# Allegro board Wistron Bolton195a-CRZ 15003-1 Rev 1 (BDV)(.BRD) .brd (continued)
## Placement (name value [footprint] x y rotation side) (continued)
PC4914  SC4D7U6D3V3KX-GP  [C603H36]  81.03 35.64 90 top
PC4915  SC1U6D3V2KX-GP  [C402H22]  86.84 37.5 270 top
PC4916  SC22P50V2JN-4DLGP  [C402H22]  71.11 26.53 270 top
PC4917  SC1U25V3KX-1-GP  [C603H36]  74.05 35.88 180 top
PC4918  SC22P50V2JN-4DLGP  [C402H22]  71.19 36.46 90 top
PC4919  SC18P50V2JN-1DLGP  [C402H22]  71.12 33.52 270 top
PC4920  SC18P50V2JN-1DLGP  [C402H22]  71.12 30.54 270 top
PC4921  SCD1U16V2KX-3GP  [C402H22]  73.26 24.94 90 top
PC4922  SC10U25V6KX-1GP  [C1206H71]  92.91 21 270 top
PC4923  SC10U25V6KX-1GP  [C1206H71]  92.91 23.22 270 top
PC5001  SC1U10V2KX-1GP  [C402H22]  110.95 127.2 270 bottom
PC5002  SC1KP50V2KX-1DLGP  [C402H22]  110.95 126.32 270 bottom
PC5005  SCD1U50V3KX-GP  [C603H36]  114.63 135.15 90 bottom
PC5006  SC10U25V6KX-1GP  [C1206H71]  114.49 131.25 90 bottom
PC5007  SC10U25V6KX-1GP  [C1206H71]  114.49 133.44 90 bottom
PC5008  SCD1U50V3KX-GP  [C603H36]  112.89 125.57 180 bottom
PC5009  SC10U10V5KX-2GP  [C805H54]  114.48 118.4 180 bottom
PC5010  SC1KP50V2KX-1GP  [C402H22]  111.81 140.58 0 top
PC5011  SCD1U16V2KX-3GP  [C402H22]  114.2 153.55 0 bottom
PC5012  SC22U6D3V3MX-1-GP  [C603H40]  115.28 153.66 0 bottom
PC5013  SC18P50V2JN-1DLGP  [C402H22]  107.76 118.17 90 bottom
PC5014  SC10U10V5KX-2DLGP  [C805H50]  112.26 113.32 180 bottom
PC5015  SC10U10V5KX-2GP  [C805H54]  110.08 113.32 180 bottom
PC5016  SCD033U25V3KX-GP  [C603]  109.79 117.17 180 bottom
PC5101  SC10U6D3V3MX-GP  [C603H38]  14.31 132.52 90 top
PC5102  SC10U6D3V3MX-GP  [C603H38]  14.31 131.25 90 top
PC5103  SC1U6D3V2KX-GP  [C402H22]  10.89 135.91 180 top
PC5104  SC1KP50V2KX-1DLGP  [C402H22]  16.61 135.52 180 bottom
PC5105  SC22U6D3V3MX-1-GP  [C603H40]  28.17 132.5 90 top
PC5106  SC22U6D3V3MX-1-GP  [C603H40]  28.16 131.3 90 top
PC5107  SC22U6D3V3MX-1-DL-GP  [C603H40]  28.16 130.12 90 top
PC5108  SC22P50V2JN-4GP  [C402H22]  11.08 137.84 180 top
PC5109  SC680P50V2KX-2DLGP  [C402H22]  12.74 138.15 90 top
PC5110  SCD1U10V2KX-5DLGP  [C402H22]  16 138.47 270 top
PC5203  SCD1U10V2KX-5DLGP  [C402H22]  53.08 20 0 top
PC5204  SC1U10V2KX-1GP  [C402H22]  108.76 126.24 90 bottom
PC5205  SC22U6D3V3MX-1-GP  [C603H40]  51.26 20.35 90 top
PC5206  SC22U6D3V3MX-1-GP  [C603H40]  51.46 27.36 180 top
PC5207  SC22U6D3V3MX-1-GP  [C603H40]  116.51 153.66 0 bottom
PC5208  SCD1U50V3KX-GP  [C603H36]  77.73 36.11 270 top
PC5210  SC22U6D3V3MX-1-GP  [C603H40]  24.88 164.16 90 top
PC5211  SC22U6D3V3MX-1-GP  [C603H40]  24.88 162.97 90 top
PC5212  SC22U6D3V3MX-1-GP  [C603H40]  24.88 161.77 90 top
PC5213  SC22U6D3V3MX-1-GP  [C603H40]  24.88 160.55 90 top
PC5214  SC22U6D3V3MX-1-GP  [C603H40]  24.88 159.33 90 top
PC5215  SC22U6D3V3MX-1-GP  [C603H40]  24.89 158.12 90 top
PC5216  SC22U6D3V3MX-1-GP  [C603H40]  44.93 175.67 90 bottom
PC5217  SC22U6D3V3MX-1-GP  [C603H40]  44.93 176.86 90 bottom
PC5218  SC22U6D3V3MX-1-GP  [C603H40]  44.93 178.05 90 bottom
PC5219  SC22U6D3V3MX-1-GP  [C603H40]  44.93 179.25 90 bottom
PC5220  SC22U6D3V3MX-1-GP  [C603H40]  44.93 180.44 90 bottom
PC5221  SC22U6D3V3MX-1-GP  [C603H40]  44.93 181.64 90 bottom
PC5222  SC22U6D3V3MX-1-GP  [C603H40]  66.09 182.17 270 bottom
PC5223  SC22U6D3V3MX-1-GP  [C603H40]  66.09 180.9 270 bottom
PC5224  SC22U6D3V3MX-1-GP  [C603H40]  44.93 173.25 90 bottom
PC5225  SC22U6D3V3MX-1-GP  [C603H40]  44.93 174.45 90 bottom
PC5226  SC22U6D3V3MX-1-GP  [C603H40]  44.96 182.85 90 bottom
PC5229  SC22U6D3V3MX-1-GP  [C603H40]  44.93 172.03 90 bottom
PG4401  COPPER-CLOSE-GP-U  [CON2C-U]  16.66 171.4 0 top
PG4402  COPPER-CLOSE-GP-U  [CON2C-U]  16.66 168.55 180 top
PG4403  COPPER-CLOSE-GP-U  [CON2C-U]  55.57 179.49 180 top
PG4404  COPPER-CLOSE-GP-U  [CON2C-U]  55.42 184.87 0 top
PG4801  GAP-CLOSE-PWR-3-GP  [GAP-CLOSE-PWR-3]  29.52 116.81 270 top
PG4802  GAP-CLOSE-PWR-3-GP  [GAP-CLOSE-PWR-3]  62.79 139.27 0 bottom
PG4901  GAP-CLOSE-PWR-3-GP  [GAP-CLOSE-PWR-3]  80.55 33.87 0 top
PG4902  GAP-CLOSE-PWR-3-GP  [GAP-CLOSE-PWR-3]  70.78 24.2 270 top
PG4903  GAP-CLOSE-PWR-3-GP  [GAP-CLOSE-PWR-3]  86.89 38.45 180 top
PG4904  GAP-CLOSE-PWR-3-GP  [GAP-CLOSE-PWR-3]  81.48 37.19 0 top
PG4905  GAP-CLOSE-PWR-3-GP  [GAP-CLOSE-PWR-3]  113.13 153.5 90 bottom
PL4901  IND-3D3UH-116-GP-U  [L686647-127318H119]  86.35 16.05 90 top
PL4902  IND-3D3UH-116-GP-U  [L686647-127318H119]  92.55 34.15 180 top
PL4904  IND-D36UH-19-GP  [L115100-2H158]  55.52 182.14 0 top
PL4905  IND-D33UH-12-GP-U  [L686647-127318H119]  16.66 170.03 0 top
PL4906  IND-1D5UH-53-GP-U  [L686647-127318H119]  22.44 125.71 90 top
PL5001  IND-1D5UH-53-GP-U  [L686647-127318H119]  114.86 146.97 0 bottom
PL5101  IND-1D5UH-53-GP-U  [L686647-127318H119]  22.26 133.39 90 top
PQ4401  AON6520-GP  [PPAK-8P-5262H40]  13.64 179.78 0 top
PQ4402  AON6510-GP  [PPAK-8P-5262H40]  20.24 178 180 top
PQ4403  AON6520-GP  [PPAK-8P-5262H40]  67.37 189.83 90 bottom
PQ4404  AON6510-GP  [PPAK-8P-5262H40]  58.72 189.13 0 bottom
PQ4405  AON6510-GP  [PPAK-8P-5262H40]  52.16 189.15 0 bottom
PQ4801  AON7410-GP  [PPAK-8P-3232H36]  14.54 127.37 90 top
PQ4802  AON7506-GP  [PPAK-8P-3232H36]  16.05 122.97 270 top
PQ4901  AON7410-GP  [PPAK-8P-3232H36]  94.29 17.5 270 top
PQ4902  AON7410-GP  [PPAK-8P-3232H36]  94.98 26.24 180 top
PQ4903  AON7506-GP  [PPAK-8P-3232H36]  92.8 13.04 90 top
PQ4904  AON7506-GP  [PPAK-8P-3232H36]  90.53 27.74 0 top
PQ5001  AON7410-GP  [PPAK-8P-3232H36]  116.81 138.81 0 bottom
PQ5002  AON7506-GP  [PPAK-8P-3232H36]  112.39 140.31 180 bottom
PR1  D01R2512F-3-GP  [R2512H32]  126.75 16.26 270 top
PR2  300KR2F-GP  [R402H16]  126.24 8.46 0 bottom
PR3  30KR2F-GP  [R402H16]  121.26 11.89 270 bottom
PR4  30KR2F-GP  [R402H16]  132.16 14.25 0 top
PR7  300KR2F-GP  [R402H16]  129.57 13.51 270 top
PR10  15KR2F-GP  [R402H16]  127.94 6.88 90 bottom
PR11  15KR2F-GP  [R402H16]  118.59 10.92 90 bottom
PR12  100KR2F-L1-GP  [R402H16]  116.05 12.65 0 top
PR13  15KR2F-GP  [R402H16]  116.56 10.92 90 bottom
PR14  20KR2J-L2-GP  [R402H16]  109.6 18.99 180 top
PR15  20KR2J-L2-GP  [R402H16]  110.75 18.95 180 top
PR16  100KR2F-L1-GP  [R402H16]  115.01 12.65 180 top
PR17  200KR2F-L-GP  [R402H16]  119.51 20.16 0 top
PR18  100KR2J-1-GP  [R402H16]  116.41 19.74 270 top
PR161  10KR2J-3-GP  [R402H16]  36.07 75.18 270 top
PR4202  10KR2F-2-GP  [R402H16]  128.35 8.46 180 bottom
PR4401  27K4R2F-GP  [R402H16]  33.56 177.57 270 top
PR4402  10R2F-L-GP  [R402H14]  27.22 179.07 0 top
PR4403  0R0402-PAD-2-GP  [0R0402-PAD-1]  28.28 179.08 0 top
PR4404  2K05R2F-GP  [R402H16]  27.19 187.62 180 top
PR4405  -  [0R0805-PAD]  16.77 192.56 180 top
PR4406  -  [0R0805-PAD]  18.77 192.56 180 top
PR4407  499R2F-2-GP  [R402H16]  26.76 186 270 top
PR4408  5K62R2F-DL-GP  [R402H16]  32.33 189.12 270 bottom
PR4409  10R2F-L-GP  [R402H14]  27.63 181.19 270 top
PR4410  2K61R2F-1-GP  [R402H16]  32.57 179.08 0 top
PR4411  267KR2F-GP  [R402H16]  28.68 187.19 90 top
PR4412  1K6R2F-GP  [R402H16]  28.23 185.72 0 top
PR4413  825R2F-GP  [R402H16]  29.65 181.11 180 top
PR4414  11KR2F-L-GP  [R402H16]  31.16 183.55 270 top
PR4415  2D2R5J-1-GP  [R805H24]  15.06 179.55 180 bottom
PR4416  NTC-10K-27-GP-U  [NTC-402H24-U]  12.37 169.34 180 top
PR4417  2D2R5J-1-GP  [R805H24]  28.18 194.18 270 top
PR4418  1K2R2F-1-GP  [R402H16]  30.27 184.59 270 top
PR4420  2D2R5J-1-GP  [R805H24]  20.44 180.83 0 bottom
PR4421  3K83R2F-GP  [R402H16]  34 176.09 180 top
PR4422  NTC-470K-8-GP-U  [NTC-402H22-U]  11.3 183.49 90 top
PR4423  3K65R2F-1-GP  [R402H16]  31.5 179.08 180 top
PR4424  10R2F-L-GP  [R402H14]  29.97 177.89 270 top
PR4425  133KR2F-GP  [R402H16]  33.24 187.06 180 bottom
PR4426  1R5J-2-GP  [R805H24]  31.77 196.33 0 top
PR4427  1R5J-2-GP  [R805H24]  33.73 196.33 0 top
PR4428  0R0402-PAD-2-GP  [0R0402-PAD-1]  33.51 182.54 180 top
PR4429  0R0402-PAD-2-GP  [0R0402-PAD-1]  36.1 179.21 180 top
PR4430  0R0402-PAD-2-GP  [0R0402-PAD-1]  36.51 182.48 180 top
PR4431  0R0402-PAD-2-GP  [0R0402-PAD-1]  38.36 179.91 180 top
PR4432  -  [0R0805-PAD]  67.5 195.82 0 bottom
PR4433  -  [0R0805-PAD]  69.47 195.83 0 bottom
PR4434  133KR2F-GP  [R402H16]  35.16 187.05 0 bottom
PR4435  27K4R2F-GP  [R402H16]  40.13 183.52 270 top
PR4437  0R0402-PAD-2-GP  [0R0402-PAD-1]  38.97 177.76 180 bottom
PR4438  3K83R2F-GP  [R402H16]  41.62 183.25 0 top
PR4439  NTC-470K-8-GP-U  [NTC-402H22-U]  66.54 185.64 270 bottom
PR4440  0R0402-PAD-2-GP  [0R0402-PAD-1]  43.51 183.34 180 top
PR4441  10R2F-L-GP  [R402H14]  36.63 189.77 90 bottom
PR4442  2D2R5J-1-GP  [R805H24]  57.23 190.27 90 top
PR4443  10KR2F-2-GP  [R402H16]  36.63 187.81 90 bottom
PR4444  0R0402-PAD-2-GP  [0R0402-PAD-1]  37.92 177.78 180 bottom
PR4445  2D2R5J-1-GP  [R805H24]  37.73 195.24 0 bottom
PR4446  499R2F-2-GP  [R402H16]  43.78 185.44 180 top
PR4447  10R2J-2-GP  [R402H14]  44.61 183.33 0 top
PR4448  NTC-10K-27-GP-U  [NTC-402H24-U]  49.19 184.33 180 top
PR4449  0R2J-2-GP  [R402H16]  44.81 185.43 180 top
PR4450  499R2F-2-GP  [R402H16]  41.19 190.2 0 top
PR4451  11KR2F-L-GP  [R402H16]  40.83 186.71 180 top
PR4452  0R0402-PAD-2-GP  [0R0402-PAD-1]  42.66 190.67 90 top
PR4453  2K61R2F-1-GP  [R402H16]  46.37 184.94 270 top
PR4454  0R0402-PAD-2-GP  [0R0402-PAD-1]  36.89 177.77 180 bottom
PR4455  2D2R5J-1-GP  [R805H24]  47.85 192.93 0 bottom
PR4456  34KR2F-GP  [R402H16]  42.66 191.71 90 top
PR4457  2K15R2F-1-GP  [R402H16]  42.33 188.99 0 top
PR4458  10R2F-L-GP  [R402H14]  43.81 188.54 90 top
PR4459  1KR2F-3-GP  [R402H16]  43.81 189.61 90 top
PR4460  0R2J-2-GP  [R402H16]  36.63 190.81 90 bottom
PR4461  3K65R2F-1-GP  [R402H16]  46.35 186.02 270 top
PR4462  10R2F-L-GP  [R402H14]  47.52 183.36 180 top
PR4463  10KR2J-3-GP  [R402H16]  61.62 192.18 180 top
PR4464  10KR2J-3-GP  [R402H16]  15.39 175.64 180 bottom
PR4801  10KR2J-3-GP  [R402H16]  13.61 116.28 0 top
PR4802  -  [0R0805-PAD]  10.08 128.09 90 top
PR4804  2D2R5J-1-GP  [R805H24]  17.02 125.32 0 bottom
PR4805  78K7R2F-GP  [R402H16]  14.23 111.16 90 top
PR4806  2D2R5J-1-GP  [R805H24]  14.78 119.74 90 top
PR4808  -  [0R0805-PAD]  30.21 123.12 270 top
PR4809  470KR2F-GP  [R402H16]  19.14 113.71 90 top
PR4810  -  [0R0805-PAD]  30.21 121.09 270 top
PR4811  -  [0R0805-PAD]  30.21 119.05 270 top
PR4812  2D2R5J-1-GP  [R805H24]  15.66 130.62 90 bottom
PR4813  11K8R2F-GP  [R402H16]  18.75 111.29 0 top
PR4814  10R2F-L-GP  [R402H14]  31.5 102.75 0 top
PR4815  33KR2F-GP  [R402H16]  17.7 110.7 0 top
PR4901  100KR2J-1-GP  [R402H16]  80.63 29.32 270 top
PR4902  -  [0R0805-PAD]  99.11 25.4 90 bottom
PR4903  -  [0R0805-PAD]  99.11 23.47 90 bottom
PR4904  -  [0R0805-PAD]  99.11 21.51 90 bottom
PR4905  2D2R5J-1-GP  [R805H24]  83.39 27.71 270 top
PR4906  -  [0R0805-PAD]  86.91 41.35 90 top
PR4907  -  [0R0805-PAD]  86.91 42.74 90 top
PR4908  2D2R5J-1-GP  [R805H24]  77.32 24.22 270 top
PR4909  2D2R5J-1-GP  [R805H24]  77.29 37.78 90 top
PR4910  -  [0R0805-PAD]  86.91 44.14 90 top
PR4911  2D2R5J-1-GP  [R805H24]  88.04 16.21 270 bottom
PR4912  2D2R5J-1-GP  [R805H24]  89.43 28.63 270 bottom
PR4913  -  [0R0805-PAD]  86.91 39.95 90 top
PR4914  -  [0R0805-PAD]  69.46 18.3 90 top
PR4915  -  [0R0805-PAD]  69.46 19.7 90 top
PR4916  -  [0R0805-PAD]  69.46 21.1 90 top
PR4917  6K65R2F-GP  [R402H16]  71.12 27.49 90 top
PR4918  15KR2F-GP  [R402H16]  71.18 35.5 270 top
PR4919  2D2R5J-1-GP  [R805H24]  87.31 26.19 0 top
PR4920  2D2R5J-1-GP  [R805H24]  83.61 11.32 270 top
PR4921  10KR2F-2-GP  [R402H16]  71.12 28.51 270 top
PR4922  21K5R2F-GP  [R402H16]  81.62 31.61 270 top
PR4923  10KR2F-2-GP  [R402H16]  71.18 34.48 270 top
PR4924  68KR2F-GP  [R402H16]  71.11 31.51 270 top
PR4925  10KR2F-2-GP  [R402H16]  81.59 30.54 90 top
PR4926  133KR2F-GP  [R402H16]  71.1 32.55 270 top
PR4927  88K7R2F-GP  [R402H16]  71.13 29.55 270 top
PR4928  0R0402-PAD-2-GP  [0R0402-PAD-1]  72.82 26.45 180 top
PR4929  10KR2J-3-GP  [R402H16]  71.77 24.14 0 top
PR4930  -  [0R0805-PAD]  69.46 22.49 90 top
PR5001  5D1R2F-GP  [R402H16]  108.33 128.57 90 bottom
PR5002  -  [0R0805-PAD]  117.13 126.92 0 bottom
PR5004  5K1R2F-2-GP  [R402H16]  110.95 125.36 270 bottom
PR5005  -  [0R0603-PAD]  108.35 127.33 90 bottom
PR5006  10KR2F-2-GP  [R402H16]  106.32 125.88 180 bottom
PR5007  2D2R5J-1-GP  [R805H24]  114.53 123.93 0 bottom
PR5008  620KR2F-GP  [R402H16]  106.45 124.16 270 bottom
PR5009  2D2R5J-1-GP  [R805H24]  118.76 140.37 180 top
PR5011  -  [0R0805-PAD]  114.48 118.39 180 top
PR5013  -  [0R0805-PAD]  104.13 151.14 270 bottom
PR5015  -  [0R0805-PAD]  104.14 149.74 270 bottom
PR5016  -  [0R0805-PAD]  104.14 148.35 270 bottom
PR5017  -  [0R0805-PAD]  104.13 146.95 270 bottom
PR5018  0R0402-PAD-2-GP  [0R0402-PAD-1]  105.08 145 0 bottom
PR5019  2D2R5J-1-GP  [R805H24]  111.81 136.28 0 top
PR5020  39K2R2F-L-GP  [R402H16]  106.89 115.98 90 bottom
PR5021  -  [0R0805-PAD]  108.12 113.31 180 bottom
PR5022  0R2F-1-GP  [R402H16]  106.31 117.23 90 bottom
PR5101  0R0805-PAD-2-GP-U  [0R0805-PAD-1-U]  9.52 133.94 90 top
PR5102  0R0805-PAD-2-GP-U  [0R0805-PAD-1-U]  28.75 134.08 90 top
PR5103  5D1R2F-GP  [R402H16]  11.95 135 180 top
PR5104  2D2R5J-1-GP  [R805H24]  15.67 132.57 90 bottom
PR5105  102KR2F-GP  [R402H16]  10.09 137.83 180 top
PR5107  51KR2F-L-GP  [R402H16]  12.06 139.86 180 top
PR5108  18KR2F-GP  [R402H16]  14.47 139.01 180 top
PR5201  0R0603-PAD-2-GP-U  [0R0603-PAD-1-U]  49.92 19.14 90 top
PR5204  0R0603-PAD-2-GP-U  [0R0603-PAD-1-U]  52.68 27.36 180 top
PR5206  100KR2F-L1-GP  [R402H16]  54.05 20.02 0 top
PR5208  10KR2F-2-GP  [R402H16]  16.01 139.43 270 top
PR5209  10KR2F-2-GP  [R402H16]  14.08 140.57 90 top
PR5210  10R2F-L-GP  [R402H14]  113.13 157.43 0 bottom
PR5211  0R0805-PAD-2-GP-U  [0R0805-PAD-1-U]  28.75 136.13 90 top
PR5212  0R0805-PAD-2-GP-U  [0R0805-PAD-1-U]  9.52 131.91 90 top
PR5213  -  [0R0805-PAD]  104.13 152.54 270 bottom
PT4402  SE560U2D5VM-1-GP  [SE361416H237]  15.72 161.54 270 top
PT4403  SE560U2D5VM-1-GP  [SE361416H237]  15.72 153.9 270 top
PT4404  SE330U2D5VDM-2GP  [CT7343H83]  18.73 157.92 180 bottom
PT4406  SE560U2D5VM-1-GP  [SE361416H237]  45.28 178.49 270 top
PT4407  SE560U2D5VM-1-GP  [SE361416H237]  65.82 178.42 90 top
PT4411  SE560U2D5VM-1-GP  [SE361416H237]  23.29 118.08 270 top
PT4902  SE220U6D3VM-8GP  [SE331721H237]  78.01 15.48 0 top
PT4903  SE220U6D3VM-8GP  [SE331721H237]  93.49 42.55 90 top
PT5001  SE330U2D5VDM-2GP  [CT7343H83]  108.56 152.23 0 bottom
PU1  AP2138N-1D5TRG1-GP  [SOT23-2D8-312H58]  102.9 78.44 180 top
PU2  AO4407AL-GP  [SOIC8H69]  115.16 16.41 90 top
PU4401  ISL62771HRTZ-GP-U  [QFN40-G3D5H32]  34.52 189.11 180 top
PU4801  RT8237CZQW-2-GP  [DFN10G3-G265175H32]  16.18 114.22 180 top
PU4901  RT8243BZQW-GP  [QFN20-G1D75H32]  76.11 30.82 90 top
PU5001  RT8207MZQW-GP-U  [QFN20-G1D75H32]  110.59 121.64 0 bottom
PU5101  RT8068AZQWID-GP-U  [DFN10G3-G265175H32]  15.2 135.14 270 top
PU5201  S-1339D15-M5001-GP  [SOT-23-5H52]  50.8 23.72 0 top
PWRBT1  ACES-CON6-21-GP  [88511-0641]  125 7.45 0 top
Q1  2N7002-11-GP  [SOT23DGS2D4H44]  38.56 101.88 90 top
Q2  LMBT3904LT1G-GP  [SOT23CBE2D4H44]  38.57 98.31 90 top
Q4  2N7002KDW-GP  [SOT-363H44]  118.82 22.33 270 bottom
Q26  2N7002K-2-GP  [SOT23DGS2D4H44]  33.33 71.6 0 top
Q27  2N7002KDW-GP  [SOT-363H44]  29.73 71.93 90 top
Q28  PMBS3906-GP  [SOT-23-10H44]  16.95 33.5 270 top
Q29  2N7002KDW-GP  [SOT-363H44]  17.3 38.61 90 top
Q32  PMBS3906-GP  [SOT-23-10H44]  10.64 102.07 180 bottom
Q33  2N7002A-7-GP  [SOT23DGS2D4H48]  7.5 110.91 180 bottom
Q34  2N7002KDW-GP  [SOT-363H44]  7.37 107.06 180 bottom
Q35  2N7002K-2-GP  [SOT23DGS2D4H44]  133.68 127 90 top
Q36  2N7002K-2-GP  [SOT23DGS2D4H44]  130.31 110.37 90 bottom
Q37  MMBT3904-4-GP  [SOT23CBE2D4H44]  125.38 106.41 90 bottom
Q38  2N7002K-2-GP  [SOT23DGS2D4H44]  130.31 106.36 90 bottom
Q39  2N7002-11-GP  [SOT23DGS2D4H44]  50.85 90.65 90 top
Q40  AO3418L-GP  [SOT23DGS2D8H50]  125.38 193.66 180 top
Q41  PMBS3906-GP  [SOT-23-10H44]  64.26 55.52 270 top
Q42  2N7002KDW-GP  [SOT-363H44]  67.82 54.28 180 top
Q43  AO3413L-GP  [SOT23DGS2D8H50]  104.85 195.38 90 top
Q44  PMBS3904-1-GP  [SOT-23-10H44]  109.91 195.53 0 top
Q45  2N7002KDW-GP  [SOT-363H44]  65.74 99.95 180 bottom
Q48  2N7002H-GP  [SOT23DGS2D4H44]  50.85 87.02 90 top
Q49  2N7002KDW-GP  [SOT-363H44]  67.28 61.62 180 top
Q50  2N7002H-GP  [SOT23DGS2D4H44]  38.83 91.01 270 top
Q51  2N7002H-GP  [SOT23DGS2D4H44]  38.85 87.38 270 top
Q52  PMBS3906-GP  [SOT-23-10H44]  133.22 4.72 90 top
Q57  2N7002H-GP  [SOT23DGS2D4H44]  25.38 102.09 270 bottom
Q75  2N7002A-7-GP  [SOT23DGS2D4H48]  113.69 6.27 270 bottom
Q76  2N7002KDW-GP  [SOT-363H44]  113.62 9.6 270 bottom
Q78  PA010BV-GP  [SOIC8H75]  47.7 9.25 180 top
Q82  2N7002A-7-GP  [SOT23DGS2D4H48]  37.36 71.55 90 top
Q83  2N7002A-7-GP  [SOT23DGS2D4H48]  41.22 71.55 90 top
Q98  2N7002K-2-GP  [SOT23DGS2D4H44]  74.9 75.03 90 top
Q99  2N7002K-2-GP  [SOT23DGS2D4H44]  74.81 78.72 0 top
Q100  2N7002A-7-GP  [SOT23DGS2D4H48]  37.31 13.51 0 bottom
Q101  2N7002A-7-GP  [SOT23DGS2D4H48]  17.6 17.73 90 bottom
Q4401  2N7002A-7-GP  [SOT23DGS2D4H48]  33.07 181.19 90 bottom
Q4402  MMBT3904-4-GP  [SOT23CBE2D4H44]  49.02 114.47 0 bottom
Q4801  SSM3K329R-1-GP  [SOT23DGS2D4H35]  34.87 101.82 180 top
Q4802  2N7002H-GP  [SOT23DGS2D4H44]  37.85 17.2 90 bottom
Q4803  2N7002-11-GP  [SOT23DGS2D4H44]  67.31 105.82 180 bottom
Q4804  2N7002H-GP  [SOT23DGS2D4H44]  58.37 81.13 180 top
Q4805  2N7002H-GP  [SOT23DGS2D4H44]  71.93 29.18 270 bottom
Q4806  2N7002H-GP  [SOT23DGS2D4H44]  71.93 32.77 270 bottom
Q4807  2N7002A-7-GP  [SOT23DGS2D4H48]  35.36 66.65 270 top
Q4808  2N7002K-2-GP  [SOT23DGS2D4H44]  19.08 24.16 0 top
R1  0R2J-2-GP  [R402H16]  74.64 112.85 0 bottom
R2  1KR2J-1-GP  [R402H16]  64.08 143.29 180 bottom
R3  0R2J-2-GP  [R402H16]  105.76 172.51 180 bottom
R4  39D2R2F-L-GP  [R402H16]  72.29 144.16 180 top
R5  1KR2F-3-GP  [R402H16]  107.97 171.47 0 bottom
R6  0R0402-PAD-2-GP  [0R0402-PAD-1]  108.99 170.41 0 bottom
R7  1KR2F-3-GP  [R402H16]  109.51 172.98 270 bottom
R8  1K69R2F-2-GP  [R402H16]  32 146.13 0 bottom
R9  1KR2F-3-GP  [R402H16]  30.96 146.13 180 bottom
R10  150R2F-1-GP  [R402H16]  49.2 163.63 270 top
R11  2KR2F-3-GP  [R402H16]  58.04 163.52 90 top
R12  100KR2J-1-GP  [R402H16]  54.01 155.33 180 bottom
R13  150R2F-1-GP  [R402H16]  48.83 159.79 270 top
R14  150R2F-1-GP  [R402H16]  48.83 160.83 270 top
R15  150R2F-1-GP  [R402H16]  46.66 163.19 180 top
R16  1KR2F-3-GP  [R402H16]  53.8 158.66 90 bottom
R17  1KR2F-3-GP  [R402H16]  53.8 157.64 90 bottom
R18  499R2F-2-GP  [R402H16]  47.68 163.19 180 top
R19  300R2J-4-GP  [R402H16]  56.89 162.41 90 top
R20  0R2J-2-GP  [R402H16]  57.53 160.82 0 top
R21  1KR2J-1-GP  [R402H16]  64.77 161.8 180 top
R22  300R2J-4-GP  [R402H16]  55.27 165.08 0 top
R23  1KR2J-1-GP  [R402H16]  63.75 161.81 180 top
R24  0R2J-2-GP  [R402H16]  54.64 163.56 270 top
R25  1KR2J-1-GP  [R402H16]  62.7 160.79 180 top
R26  1KR2J-1-GP  [R402H16]  69.97 167.65 90 top
R27  1KR2J-1-GP  [R402H16]  71.43 168.71 270 top
R28  511R2F-2-GP  [R402H16]  60.65 161.14 90 top
R29  511R2F-2-GP  [R402H16]  62.11 163.2 180 top
R30  1KR2J-1-GP  [R402H16]  56.83 157.6 90 bottom
R31  1KR2J-1-GP  [R402H16]  56.83 158.62 90 bottom
R32  1KR2J-1-GP  [R402H16]  61.97 158.13 0 bottom
R33  1KR2J-1-GP  [R402H16]  62.71 160.31 0 bottom
R34  0R0402-PAD-2-GP  [0R0402-PAD-1]  60.62 161.12 180 bottom
R35  0R0402-PAD-2-GP  [0R0402-PAD-1]  57.54 161.12 180 bottom
R36  0R0402-PAD-2-GP  [0R0402-PAD-1]  61.68 161.12 180 bottom
R37  0R0402-PAD-2-GP  [0R0402-PAD-1]  58.55 161.12 180 bottom
R38  0R0402-PAD-2-GP  [0R0402-PAD-1]  59.6 161.12 180 bottom
R39  1KR2J-1-GP  [R402H16]  56.5 161.12 0 bottom
R40  1KR2J-1-GP  [R402H16]  43.87 167.84 0 top
R41  1KR2J-1-GP  [R402H16]  57.1 165.64 90 top
R42  1KR2J-1-GP  [R402H16]  56.84 159.65 90 bottom
R43  1KR2J-1-GP  [R402H16]  57.1 166.66 90 top
R44  1KR2J-1-GP  [R402H16]  57.1 164.63 90 top
R45  4K7R2J-2-GP  [R402H16]  52.53 155.77 270 bottom
R46  1KR2J-1-GP  [R402H16]  67.04 159.16 90 bottom
R47  1KR2J-1-GP  [R402H16]  63.81 159.95 0 bottom
R48  1KR2J-1-GP  [R402H16]  64.52 156.97 0 bottom
R49  300R2J-4-GP  [R402H16]  66.77 161.47 270 bottom
R50  300R2J-4-GP  [R402H16]  64.32 161.41 270 bottom
R51  300R2J-4-GP  [R402H16]  66.75 160.2 90 bottom
R52  2K2R2J-2-GP  [R402H16]  54.76 166.61 270 top
R53  0R0402-PAD-2-GP  [0R0402-PAD-1]  68.22 160.64 0 bottom
R54  0R0402-PAD-2-GP  [0R0402-PAD-1]  64.85 159.95 0 bottom
R55  0R0402-PAD-2-GP  [0R0402-PAD-1]  63.49 156.98 0 bottom
R56  0R0402-PAD-2-GP  [0R0402-PAD-1]  54.26 165.08 180 top
R57  1K8R2-GP  [R402H16]  52.15 152.95 180 bottom
R58  1K8R2-GP  [R402H16]  52.56 154.56 270 bottom
R59  220R2J-L2-GP  [R402H16]  53.24 166.17 0 top
R60  0R2J-2-GP  [R402H16]  63.82 162.89 0 bottom
R61  0R2J-2-GP  [R402H16]  64.85 162.89 0 bottom
R62  47KR2J-2-GP  [R402H16]  34.62 138 90 top
R63  33R2J-2-GP  [R402H16]  85.65 83.95 180 bottom
R64  33R2J-2-GP  [R402H16]  52.62 129.52 90 top
R65  10KR2J-3-GP  [R402H16]  34.61 139.09 270 top
R67  0R0402-PAD-2-GP  [0R0402-PAD-1]  41.17 134.49 270 bottom
R69  10KR2J-3-GP  [R402H16]  62.05 127.06 90 bottom
R70  10KR2J-3-GP  [R402H16]  64.49 126.98 180 top
R71  0R2J-2-GP  [R402H16]  64.31 127.1 0 bottom
R73  10KR2J-3-GP  [R402H16]  62.05 128.14 270 bottom
R74  10KR2J-3-GP  [R402H16]  63.74 128.45 270 top
R75  0R2J-2-GP  [R402H16]  54.09 127.81 270 bottom
R76  10KR2J-3-GP  [R402H16]  58.53 126.97 270 bottom
R77  10KR2J-3-GP  [R402H16]  55.65 127.39 0 top
R78  10KR2J-3-GP  [R402H16]  50.29 125.26 270 top
R79  10KR2J-3-GP  [R402H16]  54.46 119.69 270 bottom
R80  10KR2J-3-GP  [R402H16]  48.65 127.82 0 top
R81  10KR2J-3-GP  [R402H16]  48.83 125.28 180 top
R83  10KR2J-3-GP  [R402H16]  54.1 128.84 270 bottom
R84  20MR3-GP  [R603H22]  42.29 139.61 0 top
R85  10KR2J-3-GP  [R402H16]  68.58 124.88 180 bottom
R86  100KR2J-1-GP  [R402H16]  33.42 99.4 90 top
R87  100KR2J-1-GP  [R402H16]  36.17 97.01 0 top
R88  1KR2J-1-GP  [R402H16]  52.16 129.74 0 bottom
R89  1KR2J-1-GP  [R402H16]  47.39 127.95 0 bottom
R90  1KR2J-1-GP  [R402H16]  49.66 127.82 180 top
R92  10KR2J-3-GP  [R402H16]  43.12 97.77 180 top
R93  10KR2J-3-GP  [R402H16]  52.03 131.65 0 bottom
R94  10KR2J-3-GP  [R402H16]  47.96 129.42 90 bottom
R95  10KR2J-3-GP  [R402H16]  50.68 127.82 0 top
R96  11K8R2F-GP  [R402H16]  46.43 142.01 0 bottom
R97  1KR2F-3-GP  [R402H16]  58.42 131.73 0 bottom
R98  1KR2F-3-GP  [R402H16]  59.44 131.73 0 bottom
R99  1KR2F-3-GP  [R402H16]  52.4 146.05 0 bottom
R100  1KR2F-3-GP  [R402H16]  36.86 137.26 180 bottom
R101  22R2J-2-GP  [R402H16]  54.15 122.37 90 bottom
R102  22R2J-2-GP  [R402H16]  47.95 122.9 270 top
R103  22R2J-2-GP  [R402H16]  48.39 121.87 270 top
R104  0R0402-PAD-2-GP  [0R0402-PAD-1]  48.14 130.45 90 bottom
R105  0R0402-PAD-2-GP  [0R0402-PAD-1]  46.23 124.14 180 bottom
R106  0R0402-PAD-2-GP  [0R0402-PAD-1]  43.7 127.33 180 top
R108  1MR3F-GP  [R603H22]  40.79 149.48 0 top
R109  0R0805-PAD-2-GP-U  [0R0805-PAD-1-U]  36.7 157.86 90 bottom
R110  0R0603-PAD-2-GP-U  [0R0603-PAD-1-U]  33.86 157.25 90 top
R111  0R0603-PAD-2-GP-U  [0R0603-PAD-1-U]  54.05 121.21 90 bottom
R112  0R0603-PAD-2-GP-U  [0R0603-PAD-1-U]  63.17 116.08 270 top
R113  0R0603-PAD-2-GP-U  [0R0603-PAD-1-U]  53.88 130.81 0 bottom
R115  0R0805-PAD-2-GP-U  [0R0805-PAD-1-U]  38.23 121.3 270 top
R116  0R0805-PAD-2-GP-U  [0R0805-PAD-1-U]  38.23 123.26 270 top
R117  0R0805-PAD-2-GP-U  [0R0805-PAD-1-U]  38.23 119.34 270 top
R119  0R0805-PAD-2-GP-U  [0R0805-PAD-1-U]  34.53 117.72 270 top
R121  0R0603-PAD-2-GP-U  [0R0603-PAD-1-U]  34.46 116.05 90 top
R122  10KR2J-3-GP  [R402H16]  101.68 81.76 0 top
R123  200R2J-L1-GP  [R402H16]  81.69 51.18 90 bottom
R124  1KR2J-1-GP  [R402H16]  133.73 69.85 0 top
R125  10KR2J-3-GP  [R402H16]  85.19 86.39 90 bottom
R126  10KR2J-3-GP  [R402H16]  104.75 100.01 180 top
R127  10KR2J-3-GP  [R402H16]  42.62 130.68 180 top
R128  10KR2J-3-GP  [R402H16]  58.1 128.5 0 bottom
R129  10KR2J-3-GP  [R402H16]  48.44 127.95 0 bottom
R130  0R2J-2-GP  [R402H16]  60.66 162.16 90 top
R131  2K2R2J-2-GP  [R402H16]  83.39 85.1 270 bottom
R132  2KR2J-1-GP  [R402H16]  105.89 100 0 top
R133  2KR2J-1-GP  [R402H16]  42.41 132.2 90 top
R134  2K2R2J-2-GP  [R402H16]  56.06 131.44 0 bottom
R135  2K2R2J-2-GP  [R402H16]  49.51 127.97 180 bottom
R136  0R0402-PAD-2-GP  [0R0402-PAD-1]  103.94 107.98 0 bottom
R139  1KR2F-3-GP  [R402H16]  106.82 171.47 0 bottom
R140  1KR2F-3-GP  [R402H16]  104.51 135.28 180 bottom
R141  1KR2F-3-GP  [R402H16]  104.19 174.61 90 bottom
R142  1KR2F-3-GP  [R402H16]  104.28 132 90 bottom
R145  0R0402-PAD-2-GP  [0R0402-PAD-1]  107.33 172.99 270 bottom
R146  0R0402-PAD-2-GP  [0R0402-PAD-1]  104.73 129.21 180 bottom
R152  0R0402-PAD-2-GP  [0R0402-PAD-1]  128.47 38.63 180 bottom
R164  0R0402-PAD-2-GP  [0R0402-PAD-1]  133.21 39.03 180 top
R165  0R0402-PAD-2-GP  [0R0402-PAD-1]  109.07 37.77 270 top
R166  0R0402-PAD-2-GP  [0R0402-PAD-1]  109.07 38.84 270 top
R167  0R0402-PAD-2-GP  [0R0402-PAD-1]  132.69 28.91 180 bottom
R168  0R0402-PAD-2-GP  [0R0402-PAD-1]  128.47 38.66 180 top
R169  20KR2F-L-GP  [R402H16]  123.83 30.73 90 top
R172  39K2R2F-L-GP  [R402H16]  124.64 28.52 90 top
R174  33R2J-2-GP  [R402H16]  118.47 24.82 180 top
R175  1KR2J-1-GP  [R402H16]  115.95 20.57 180 bottom
R176  1KR2J-1-GP  [R402H16]  117.6 20.19 270 bottom
R177  10KR2J-3-GP  [R402H16]  121.41 26.67 270 top
R179  0R2J-2-GP  [R402H16]  119.71 20.24 90 bottom
R232  2K2R2J-2-GP  [R402H16]  125.86 29.59 270 top
R234  1KR2J-1-GP  [R402H16]  126.19 31.9 90 top
R235  22KR2J-GP  [R402H16]  125.86 30.73 270 top
R236  22KR2J-GP  [R402H16]  129 31.65 180 top
R238  75R2J-1-GP  [R402H16]  127.51 34.92 90 top
R240  75R2J-1-GP  [R402H16]  127.51 36.07 90 top
R259  0R0402-PAD-2-GP  [0R0402-PAD-1]  130.63 38.63 0 top
R261  0R0402-PAD-2-GP  [0R0402-PAD-1]  132.19 39.03 0 top
R264  0R0402-PAD-2-GP  [0R0402-PAD-1]  127.38 38.66 0 top
R266  300R2J-4-GP  [R402H16]  120.47 63.07 270 bottom
R268  2K49R2F-GP  [R402H16]  117.68 57 90 bottom
R269  0R5J-5-GP  [R805H24]  117.32 70.82 270 bottom
R270  0R2J-2-GP  [R402H16]  104.06 62.41 90 top
R271  0R0402-PAD-2-GP  [0R0402-PAD-1]  103.2 63.07 270 bottom
R272  0R0402-PAD-2-GP  [0R0402-PAD-1]  103.2 64.08 270 bottom
R278  0R0805-PAD-2-GP-U  [0R0805-PAD-1-U]  101.24 56.77 180 top
R284  75R3J-L-GP  [R603H22]  130.07 58.95 270 top
R285  10KR2J-3-GP  [R402H16]  106.1 62.41 90 top
R286  1KR2J-1-GP  [R402H16]  106.58 68.71 270 bottom
R287  10KR2J-3-GP  [R402H16]  109.63 69.37 270 bottom
R288  15KR2F-GP  [R402H16]  108.15 68.28 180 bottom
R296  100KR2F-L1-GP  [R402H16]  132.28 145.97 0 bottom
R299  10KR2J-3-GP  [R402H16]  24.26 108.11 180 top
R302  10KR2J-3-GP  [R402H16]  25.33 108.11 180 top
R303  10KR2J-3-GP  [R402H16]  32.26 74.47 0 top
R306  1KR2J-1-GP  [R402H16]  28.91 74.04 90 top
R307  0R0402-PAD-2-GP  [0R0402-PAD-1]  25.36 72.56 0 top
R309  10KR2J-3-GP  [R402H16]  27 70.38 90 top
R310  4K7R2J-2-GP  [R402H16]  33.32 74.47 0 top
R313  33KR2F-GP  [R402H16]  13.67 32.97 90 top
R314  0R0402-PAD-2-GP  [0R0402-PAD-1]  19.95 33.03 90 top
R315  330KR2J-L1-GP  [R402H16]  13.66 34.19 90 top
R316  47KR2J-2-GP  [R402H16]  19.47 31.33 0 top
R317  1KR2J-1-GP  [R402H16]  21.48 33.36 180 top
R318  100KR2J-1-GP  [R402H16]  16.18 35.91 270 top
R319  4K7R2J-2-GP  [R402H16]  18.21 35.92 270 top
R322  100R2F-L1-GP-U  [R402H14]  18.39 20.09 270 bottom
R338  100KR2F-L1-GP  [R402H16]  23.9 11.81 180 bottom
R339  10R2F-L-GP  [R402H14]  32.69 15.57 90 bottom
R341  10KR2F-2-GP  [R402H16]  21.72 18.87 270 bottom
R342  0R1206-PAD-1-GP  [0R1206-PAD-1]  28.04 8.71 90 bottom
R345  1KR2F-3-GP  [R402H16]  26.26 11.79 180 bottom
R346  0R0805-PAD-2-GP-U  [0R0805-PAD-1-U]  33.34 21.06 90 bottom
R347  200R5J-GP  [R805H24]  33.34 23.01 90 bottom
R348  D33R6F-GP  [R1206H26]  46.44 12.7 0 bottom
R349  D33R6F-GP  [R1206H26]  48.69 12.7 0 bottom
R350  1R5J-2-GP  [R805H24]  51.46 9 0 bottom
R353  10KR2F-2-GP  [R402H16]  31.19 12.62 180 bottom
R354  10KR2F-2-GP  [R402H16]  34.29 16.26 180 bottom
R355  300KR2F-GP  [R402H16]  30.15 12.62 180 bottom
R356  300KR2F-GP  [R402H16]  33.12 17.12 0 bottom
R359  4K7R2J-2-GP  [R402H16]  124.13 24.99 0 top
R360  4K7R2J-2-GP  [R402H16]  123.04 24.38 0 top
R364  1KR2J-1-GP  [R402H16]  22.75 106.25 90 top
R365  1KR2J-1-GP  [R402H16]  22.75 105.11 90 top
R367  20KR2J-L2-GP  [R402H16]  24.91 106.38 270 top
R374  100R2J-2-GP  [R402H14]  32.77 12.47 270 bottom
R375  100R2J-2-GP  [R402H14]  36.14 10.24 270 bottom
R376  47KR2J-2-GP  [R402H16]  9.48 97.38 0 bottom
R377  511R2F-2-GP  [R402H16]  8 114.81 90 bottom
R378  100KR2J-1-GP  [R402H16]  9.99 108.17 90 bottom
R379  1KR2J-1-GP  [R402H16]  10.69 104.54 90 bottom
R380  330KR2J-L1-GP  [R402H16]  10.53 97.38 0 bottom
R381  4K7R2J-2-GP  [R402H16]  7 102.9 0 bottom
R382  100KR2J-1-GP  [R402H16]  11.61 97.39 180 bottom
R383  4K7R2J-2-GP  [R402H16]  8.04 101.86 0 bottom
R384  1MR2J-1-GP  [R402H16]  9.54 95.32 180 bottom
R386  10KR2J-3-GP  [R402H16]  7.45 104.57 90 bottom
R387  499R2F-2-GP  [R402H16]  128.73 126.97 270 bottom
R388  499R2F-2-GP  [R402H16]  130.71 127 90 bottom
R389  499R2F-2-GP  [R402H16]  129.07 121.24 0 bottom
R390  499R2F-2-GP  [R402H16]  129.07 123.2 180 bottom
R391  499R2F-2-GP  [R402H16]  129.09 117.18 0 bottom
R392  499R2F-2-GP  [R402H16]  129.09 119.16 180 bottom
R393  499R2F-2-GP  [R402H16]  129.09 113.32 0 bottom
R394  499R2F-2-GP  [R402H16]  129.09 115.25 180 bottom
R395  10KR2J-3-GP  [R402H16]  127.9 109.43 180 bottom
R396  10KR2J-3-GP  [R402H16]  127.86 105.54 180 bottom
R401  10KR2J-3-GP  [R402H16]  125.96 103.96 90 bottom
R402  1KR2J-1-GP  [R402H16]  124.9 108.95 90 bottom
R429  0R0805-PAD-2-GP-U  [0R0805-PAD-1-U]  10.68 65.12 180 bottom
R430  33R2J-2-GP  [R402H16]  21.59 80.72 270 top
R431  33R2J-2-GP  [R402H16]  21.77 75.56 90 top
R432  0R2J-2-GP  [R402H16]  48.23 90.02 180 top
R433  33R2J-2-GP  [R402H16]  22.71 78.51 90 top
R434  47KR2J-2-GP  [R402H16]  59.26 54.53 90 top
R435  47KR2J-2-GP  [R402H16]  127.82 194.34 0 top
R436  330KR2J-L1-GP  [R402H16]  59.26 56.52 90 top
R437  1KR2J-1-GP  [R402H16]  67.34 57.63 270 top
R438  100KR2J-1-GP  [R402H16]  65.18 53.01 90 top
R439  4K7R2J-2-GP  [R402H16]  70.21 53.44 180 top
R440  0R0402-PAD-2-GP  [0R0402-PAD-1]  79.43 56.39 270 bottom
R441  10KR2J-3-GP  [R402H16]  83.54 57.66 0 bottom
R463  0R3J-0-U-GP  [R603H22]  119.39 193.14 270 top
R464  300R2J-4-GP  [R402H16]  76.5 195.36 0 top
R466  10KR2J-3-GP  [R402H16]  50.9 123.8 0 top
R474  10KR2J-3-GP  [R402H16]  27.43 38.15 90 top
R475  10KR2J-3-GP  [R402H16]  28.47 33.27 270 top
R476  10KR2J-3-GP  [R402H16]  27.43 39.22 270 top
R477  10KR2J-3-GP  [R402H16]  28.47 34.42 270 top
R478  0R2J-2-GP  [R402H16]  26.52 23.67 180 top
R479  0R2J-2-GP  [R402H16]  27.58 23.7 180 top
R480  0R0402-PAD-2-GP  [0R0402-PAD-1]  78.84 181.31 180 top
R481  0R0402-PAD-2-GP  [0R0402-PAD-1]  102.31 195.42 0 top
R483  0R0402-PAD-2-GP  [0R0402-PAD-1]  101.24 195.42 0 top
R486  0R0402-PAD-2-GP  [0R0402-PAD-1]  98.76 196.14 90 top
R487  0R0402-PAD-2-GP  [0R0402-PAD-1]  96.84 195 0 top
R488  0R0402-PAD-2-GP  [0R0402-PAD-1]  95.72 194.99 0 top
R489  0R0402-PAD-2-GP  [0R0402-PAD-1]  104.75 198.02 90 top
R490  100KR2J-1-GP  [R402H16]  107.54 196.19 0 top
R491  1KR2J-1-GP  [R402H16]  98.76 195.11 90 top
R492  10KR2J-3-GP  [R402H16]  112.25 194.62 180 top
R493  10KR2J-3-GP  [R402H16]  109.18 99.46 90 top
R497  10KR2J-3-GP  [R402H16]  64.13 124.09 270 bottom
R498  10KR2J-3-GP  [R402H16]  78.81 80.38 90 top
R499  17K8R2F-GP  [R402H16]  60.7 65.13 180 bottom
R500  10KR2F-2-GP  [R402H16]  59.18 72.97 180 top
R501  10KR2J-3-GP  [R402H16]  78.82 81.48 90 top
R502  6K49R2F-1-GP  [R402H16]  68.45 71.57 90 top
R503  10KR2F-2-GP  [R402H16]  62 72.97 180 top
R504  10KR2J-3-GP  [R402H16]  61.04 90.44 180 bottom
R505  10KR2J-3-GP  [R402H16]  62.11 90.46 180 bottom
R507  10KR2F-2-GP  [R402H16]  60.55 67.64 270 top
R508  17K8R2F-GP  [R402H16]  60.2 62.25 90 bottom
R509  10KR2J-3-GP  [R402H16]  60.55 88.38 270 bottom
R510  10KR2J-3-GP  [R402H16]  63.45 80.97 90 top
R511  10KR2J-3-GP  [R402H16]  51.93 78.58 90 bottom
R512  10KR2J-3-GP  [R402H16]  51.95 79.65 90 bottom
R513  10KR2J-3-GP  [R402H16]  51.94 80.7 90 bottom
R514  10KR2F-2-GP  [R402H16]  63.02 68.33 180 top
R515  2K2R2J-2-GP  [R402H16]  43.11 88.67 90 top
R516  10KR2J-3-GP  [R402H16]  54.47 124.2 90 bottom
R517  10KR2J-3-GP  [R402H16]  73.03 64.22 90 bottom
R518  10KR2J-3-GP  [R402H16]  50.24 76.89 0 top
R519  95K3R2F-GP  [R402H16]  57.88 64.99 90 bottom
R520  10KR2J-3-GP  [R402H16]  63.15 90.47 180 bottom
R521  10KR2F-2-GP  [R402H16]  58.42 71.5 270 top
R522  0R0402-PAD-2-GP  [0R0402-PAD-1]  57.53 68.53 90 top
R523  10KR2J-3-GP  [R402H16]  63.19 88.52 180 bottom
R524  10KR2J-3-GP  [R402H16]  53.31 89.81 0 top
R526  0R0402-PAD-2-GP  [0R0402-PAD-1]  68.4 72.69 90 top
R527  4K7R2J-2-GP  [R402H16]  71.07 65.35 0 bottom
R529  4K7R2F-GP  [R402H16]  65.58 103.33 90 bottom
R530  100KR2J-1-GP  [R402H16]  65.96 93.4 0 bottom
R531  10KR2F-2-GP  [R402H16]  65.74 91.29 270 bottom
R533  10KR2J-3-GP  [R402H16]  81.25 55.37 0 bottom
R534  0R0402-PAD-2-GP  [0R0402-PAD-1]  59 77.72 270 top
R535  10KR2J-3-GP  [R402H16]  73.03 65.26 90 bottom
R536  0R0402-PAD-2-GP  [0R0402-PAD-1]  64.9 95.45 180 bottom
R537  20KR2J-L2-GP  [R402H16]  66.4 94.97 270 bottom
R538  0R0402-PAD-2-GP  [0R0402-PAD-1]  66.37 90.46 90 top
R539  33R2J-2-GP  [R402H16]  75.31 94.06 180 bottom
R540  0R0402-PAD-2-GP  [0R0402-PAD-1]  69.24 63.6 180 bottom
R541  0R0402-PAD-2-GP  [0R0402-PAD-1]  69.55 65.5 180 bottom
R542  10KR2J-3-GP  [R402H16]  72.34 90.58 0 bottom
R543  33R2J-2-GP  [R402H16]  59.61 64.64 270 top
R544  100R2F-L1-GP-U  [R402H14]  75.01 65.3 180 bottom
R545  0R0402-PAD-2-GP  [0R0402-PAD-1]  75.9 62.15 90 bottom
R546  1KR2J-1-GP  [R402H16]  76.17 65.74 180 bottom
R547  0R0402-PAD-2-GP  [0R0402-PAD-1]  78.33 87.96 180 bottom
R548  1KR2J-1-GP  [R402H16]  80.37 104.65 0 bottom
R549  1KR2J-1-GP  [R402H16]  81.46 104.65 0 bottom
R550  1KR2J-1-GP  [R402H16]  82.55 104.65 0 bottom
R551  1KR2J-1-GP  [R402H16]  77.08 104.64 0 bottom
R552  1KR2J-1-GP  [R402H16]  78.23 104.65 0 bottom
R553  1KR2J-1-GP  [R402H16]  79.3 104.65 0 bottom
R555  47KR2J-2-GP  [R402H16]  60.79 36.5 270 top
R556  10KR2J-3-GP  [R402H16]  56.97 87.27 180 top
R557  1KR2J-1-GP  [R402H16]  81.18 71.27 90 bottom
R559  100KR2J-1-GP  [R402H16]  81.94 80.42 270 top
R560  1KR2J-1-GP  [R402H16]  80.72 69.77 180 bottom
R561  10KR2J-3-GP  [R402H16]  58.73 88.46 0 bottom
R562  10KR2J-3-GP  [R402H16]  66.09 112.38 180 top
R563  10KR2J-3-GP  [R402H16]  67.97 65.38 270 top
R568  10KR2J-3-GP  [R402H16]  53.82 87.1 90 top
R572  10KR2J-3-GP  [R402H16]  55.93 87.27 180 top
R574  0R0402-PAD-2-GP  [0R0402-PAD-1]  53.8 85.12 270 top
R575  0R0402-PAD-2-GP  [0R0402-PAD-1]  72.7 61.62 180 bottom
R576  0R2J-2-GP  [R402H16]  73.76 61.61 0 bottom
R577  0R0402-PAD-2-GP  [0R0402-PAD-1]  73.03 63.15 270 bottom
R578  47KR2J-2-GP  [R402H16]  59.24 23.93 180 top
R579  1KR2J-1-GP  [R402H16]  61.52 64.64 270 top
R580  0R0402-PAD-2-GP  [0R0402-PAD-1]  61.65 62.51 90 top
R581  1KR2J-1-GP  [R402H16]  69.82 60.48 270 top
R582  1KR2J-1-GP  [R402H16]  65.23 63.3 180 top
R583  20KR2J-L2-GP  [R402H16]  63.32 62.43 0 top
R584  1KR2J-1-GP  [R402H16]  69.34 63.78 180 top
R585  0R0402-PAD-2-GP  [0R0402-PAD-1]  18.29 89.12 270 bottom
R586  100KR2J-1-GP  [R402H16]  23.85 97.49 270 top
R587  12KR2F-L-GP  [R402H16]  27.43 93.09 90 bottom
R588  0R3J-0-U-GP  [R603H22]  26.69 86.34 180 top
R589  0R0603-PAD-2-GP-U  [0R0603-PAD-1-U]  125.11 196.28 90 top
R590  0R3J-0-U-GP  [R603H22]  22.66 90.95 270 bottom
R591  4K7R2J-2-GP  [R402H16]  27.47 91.65 270 bottom
R592  4K7R2J-2-GP  [R402H16]  27.46 90.6 270 bottom
R593  0R2J-2-GP  [R402H16]  31.14 93.9 0 bottom
R594  0R2J-2-GP  [R402H16]  32.18 93.9 0 bottom
R595  0R2J-2-GP  [R402H16]  34.59 90.02 90 top
R596  0R2J-2-GP  [R402H16]  34.5 86.39 90 top
R597  4K7R2J-2-GP  [R402H16]  20.87 102.58 180 bottom
R598  4K7R2J-2-GP  [R402H16]  21.76 107.9 180 bottom
R599  4K7R2J-2-GP  [R402H16]  19.96 104.07 270 bottom
R600  4K7R2J-2-GP  [R402H16]  22.85 107.91 0 bottom
R601  4K7R2J-2-GP  [R402H16]  22.58 104.82 180 bottom
R602  0R0402-PAD-2-GP  [0R0402-PAD-1]  21.24 106.44 90 bottom
R603  0R0402-PAD-2-GP  [0R0402-PAD-1]  19.95 105.12 90 bottom
R604  4K7R2J-2-GP  [R402H16]  23.91 107.71 0 bottom
R605  4K7R2J-2-GP  [R402H16]  23.61 104.82 180 bottom
R606  4K7R2J-2-GP  [R402H16]  34.53 87.51 90 top
R607  4K7R2J-2-GP  [R402H16]  34.59 91.16 90 top
R608  4K7R2J-2-GP  [R402H16]  41.34 88.21 0 top
R609  4K7R2J-2-GP  [R402H16]  41.34 90.17 180 top
R610  100KR2J-L-GP  [R402H16]  19.37 87.06 0 bottom
R611  100KR2J-L-GP  [R402H16]  18.29 90.17 90 bottom
R613  100KR2J-L-GP  [R402H16]  18.34 87.06 180 bottom
R614  100KR2J-L-GP  [R402H16]  22.54 101.58 180 top
R615  100KR2J-L-GP  [R402H16]  22.25 98.93 0 top
R616  10KR2J-3-GP  [R402H16]  136.63 7.62 90 top
R617  4K7R2J-2-GP  [R402H16]  136.63 9.02 90 top
R618  300R5J-GP  [R805H24]  133.86 12.34 90 top
R619  2K2R2J-2-GP  [R402H16]  137.59 4.09 180 top
R620  10KR2J-3-GP  [R402H16]  136.09 4.55 270 top
R621  150R5J-GP  [R805H24]  130.35 4.72 180 top
R622  4K7R2J-2-GP  [R402H16]  104.92 3.19 270 top
R623  75R2J-1-GP  [R402H16]  103.45 3.61 0 top
R624  10KR2J-3-GP  [R402H16]  130.12 10.21 180 top
R671  10KR2J-3-GP  [R402H16]  29.06 100.56 90 bottom
R698  10KR2J-3-GP  [R402H16]  81.61 72.75 180 bottom
R802  0R5J-5-GP  [R805H24]  126.54 21.62 270 top
R803  0R5J-5-GP  [R805H24]  126.57 19.53 270 top
R804  0R5J-5-GP  [R805H24]  126.52 19.25 90 bottom
R807  150R2F-1-GP  [R402H16]  135.31 117.91 180 top
R808  0R2J-2-GP  [R402H16]  97.53 4.84 0 bottom
R809  20KR2F-L-GP  [R402H16]  98.67 4.84 0 bottom
R810  15KR2F-GP  [R402H16]  125.55 4.6 90 bottom
R812  4K7R2J-2-GP  [R402H16]  39.32 74.27 0 top
R813  300R2J-4-GP  [R402H16]  22.91 58.85 90 top
R822  10KR2J-3-GP  [R402H16]  17.07 12.95 90 top
R823  10KR2J-3-GP  [R402H16]  18.97 12.95 90 top
R824  10KR2J-3-GP  [R402H16]  20.9 12.95 90 top
R826  150R2F-1-GP  [R402H16]  135.32 114.84 180 top
R827  150R2F-1-GP  [R402H16]  135.34 123.25 180 top
R828  150R2F-1-GP  [R402H16]  135.33 120.71 180 top
R830  1KR2J-1-GP  [R402H16]  29.03 101.6 270 bottom
R832  10KR2F-2-GP  [R402H16]  56.48 66.66 270 bottom
R866  0R2J-2-GP  [R402H16]  82.42 57.65 0 bottom
R867  0R0402-PAD-2-GP  [0R0402-PAD-1]  81.1 57.66 0 bottom
R982  1KR2J-1-GP  [R402H16]  23.19 108.12 180 top
R1012  0R0402-PAD-2-GP  [0R0402-PAD-1]  66.52 85.8 180 top
R1013  0R2J-2-GP  [R402H16]  62.79 84.84 0 top
R1014  0R0402-PAD-2-GP  [0R0402-PAD-1]  34.49 69.06 270 top
R1015  0R2J-2-GP  [R402H16]  32.92 68.61 180 top
R1019  10KR2J-3-GP  [R402H16]  43.66 129.8 0 top
R1020  10KR2J-3-GP  [R402H16]  45.57 129.75 0 top
R1021  0R0805-PAD-2-GP-U  [0R0805-PAD-1-U]  13.2 161.96 90 bottom
R1022  10R2J-2-GP  [R402H14]  131.37 151.42 270 bottom
R1023  10R2J-2-GP  [R402H14]  131.36 154.94 270 bottom
R1024  10R2J-2-GP  [R402H14]  132.52 134.94 270 bottom
R1025  10R2J-2-GP  [R402H14]  132.17 136.48 90 bottom
R1026  10R2J-2-GP  [R402H14]  131.13 148.54 270 bottom
R1027  10R2J-2-GP  [R402H14]  132.27 138.95 90 bottom
R1028  10KR2F-2-GP  [R402H16]  35.41 17.09 0 bottom
R1029  10KR2F-2-GP  [R402H16]  34.26 14.33 0 bottom
R1030  10KR2F-2-GP  [R402H16]  15.19 17.98 180 bottom
R1031  330R3J-L-GP  [R603H22]  68.4 73.79 90 top
R4401  4K7R2J-2-GP  [R402H16]  37.21 179.2 180 top
R4402  4K7R2J-2-GP  [R402H16]  49.21 117.31 0 bottom
R4403  4K7R2J-2-GP  [R402H16]  45.26 117.44 90 bottom
R4801  0R0402-PAD-2-GP  [0R0402-PAD-1]  16.74 143.79 270 top
R4802  0R2J-2-GP  [R402H16]  12.07 141.78 180 top
R4803  0R2J-2-GP  [R402H16]  13.35 143.1 0 top
R4804  0R2J-2-GP  [R402H16]  32.55 102.74 180 top
R5002  0R2J-2-GP  [R402H16]  105.36 120.87 0 bottom
R5101  0R2J-2-GP  [R402H16]  14.07 141.6 270 top
R5201  0R0402-PAD-2-GP  [0R0402-PAD-1]  16.74 142.65 270 top
R5202  0R2J-2-GP  [R402H16]  14.83 142.66 90 top
R6103  0R0603-PAD-2-GP-U  [0R0603-PAD-1-U]  27.97 31.13 0 bottom
R6104  0R0402-PAD-2-GP  [0R0402-PAD-1]  26.42 35.46 270 top
R6105  10KR2F-2-GP  [R402H16]  26.42 34.37 270 top
R6110  0R2J-2-GP  [R402H16]  28.47 35.48 90 top
R6511  22KR2J-GP  [R402H16]  110.62 51.18 90 bottom
R6512  2K2R2J-2-GP  [R402H16]  111.07 49.39 0 bottom
R6513  0R2J-2-GP  [R402H16]  101.16 50.86 180 bottom
R6515  0R2J-2-GP  [R402H16]  107.9 50.64 0 bottom
R6516  4K7R2J-2-GP  [R402H16]  102.21 50.87 0 bottom
R6517  8K2R2F-1-GP  [R402H16]  102.79 54.14 270 bottom
R6531  0R2J-2-GP  [R402H16]  105.59 50.92 0 bottom
R6532  10KR2F-2-GP  [R402H16]  40.36 15.7 180 bottom
R6533  10KR2J-3-GP  [R402H16]  67.06 108.41 270 bottom
R6534  10KR2J-3-GP  [R402H16]  67.54 103.38 90 bottom
R6535  10KR2J-3-GP  [R402H16]  57.84 83.54 270 top
R6536  0R0805-PAD-2-GP-U  [0R0805-PAD-1-U]  64.24 37.22 90 bottom
R6537  0R0805-PAD-2-GP-U  [0R0805-PAD-1-U]  64.22 39.17 90 bottom
R6538  0R0805-PAD-2-GP-U  [0R0805-PAD-1-U]  62.81 20.6 270 top
R6539  0R0805-PAD-2-GP-U  [0R0805-PAD-1-U]  62.81 18.57 270 top
R6540  0R2J-2-GP  [R402H16]  71.09 87.38 180 top
R6541  0R0402-PAD-2-GP  [0R0402-PAD-1]  70.05 87.38 180 top
R6543  10KR2J-3-GP  [R402H16]  56.39 85.78 270 top
R6544  200R2J-L1-GP  [R402H16]  81.69 50.11 90 bottom
R6545  10KR2J-3-GP  [R402H16]  52.35 77.1 0 bottom
R6546  10KR2J-3-GP  [R402H16]  65.02 114.35 0 top
R6547  1KR2J-1-GP  [R402H16]  65.01 112.38 180 top
R6548  10KR2J-3-GP  [R402H16]  63.95 114.35 0 top
R6549  1KR2J-1-GP  [R402H16]  63.94 112.38 180 top
R6550  4K7R2J-2-GP  [R402H16]  38.23 65.79 270 top
R6551  4K7R2J-2-GP  [R402H16]  106.86 3.21 270 top
R6552  1KR2J-1-GP  [R402H16]  117.74 24.81 180 bottom
R6553  1KR2J-1-GP  [R402H16]  116.69 24.81 180 bottom
R6554  1KR2J-1-GP  [R402H16]  123.18 25.56 180 bottom
R6555  1KR2J-1-GP  [R402H16]  124.28 25.57 180 bottom
R6556  0R0603-PAD-2-GP-U  [0R0603-PAD-1-U]  74.26 5.13 270 top
R6557  10KR2J-3-GP  [R402H16]  102.88 107.98 0 bottom
R6558  10KR2J-3-GP  [R402H16]  106.16 111.35 270 bottom
R6559  10KR2J-3-GP  [R402H16]  55.48 79.84 90 top
R6560  10KR2J-3-GP  [R402H16]  55.47 78.77 270 top
R6561  10KR2J-3-GP  [R402H16]  70.99 26.82 270 bottom
R6562  0R2J-2-GP  [R402H16]  38.35 69.09 270 top
R6563  10KR2J-3-GP  [R402H16]  38.35 68.07 270 top
R6564  10KR2J-3-GP  [R402H16]  40.34 13.72 0 bottom
R6565  0R2J-2-GP  [R402H16]  41.55 16.43 180 top
R6566  10KR2J-3-GP  [R402H16]  42.62 16.43 0 top
R6568  0R2J-2-GP  [R402H16]  69.63 33.17 180 top
R6569  0R2J-2-GP  [R402H16]  69.66 29.84 180 top
R6570  1KR2J-1-GP  [R402H16]  49.99 29.36 90 bottom
R6571  1KR2J-1-GP  [R402H16]  121.84 192.94 0 top
R6572  0R0603-PAD-2-GP-U  [0R0603-PAD-1-U]  122.96 193.32 180 top
R6573  1KR2J-1-GP  [R402H16]  69.01 87.38 0 top
R6574  1KR2J-1-GP  [R402H16]  33.53 155.24 90 top
R6575  2KR2J-1-GP  [R402H16]  28.57 112.39 0 top
R6576  1KR2J-1-GP  [R402H16]  27.48 108.92 180 top
R6577  20KR2J-L2-GP  [R402H16]  26.26 110.87 180 top
R6578  10KR2J-3-GP  [R402H16]  26.37 108.92 180 top
R6579  5K6R2F-2-GP  [R402H16]  21.72 19.94 270 bottom
RJ1  RJ45-8P-155-GP-U  [C100LS-10809-L]  143.14 49.5 90 top
RN1  SRN10KJ-11-GP-U  [SMD-ARES4-2H18-U]  25.43 101.6 0 top
RN2  SRN33J-7-GP-U  [ARES8-CN24-UH20]  39.95 132.06 0 top
RN3  SRN2K2J-1-GP  [ARES2H16]  53.95 127.47 0 top
RN4  SRN10KJ-6-GP  [ARES8-CN24-MUH20]  42.02 136.48 90 bottom
RN5  SRN2K2J-1-GP  [ARES2H16]  66.52 126.57 180 bottom
RN6  SRN10KJ-6-GP  [ARES8-CN24-MUH20]  11.63 75.63 270 bottom
RN7  SRN10KJ-6-GP  [ARES8-CN24-MUH20]  82.73 192.04 90 bottom
RN8  SRN33J-5-GP-U  [SMD-ARES4H18]  50.44 63.5 0 top
RN9  SRN10KJ-6-GP  [ARES8-CN24-MUH20]  89.94 97.84 180 bottom
RN10  SRN10KJ-5-GP  [ARES2H18]  74.32 89.56 0 bottom
RN11  SRN10KJ-6-GP  [ARES8-CN24-MUH20]  66.45 63.73 0 bottom
RN12  SRN2K2J-1-GP  [ARES2H16]  77.7 65.81 180 bottom
RN15  SRN2K2J-1-GP  [ARES2H16]  83.91 77.49 90 bottom
RN16  SRN2K2J-1-GP  [ARES2H16]  126.87 111.4 270 bottom
RN17  SRN2K2J-1-GP  [ARES2H16]  130.58 110.19 0 top
RN18  SRN10KJ-5-GP  [ARES2H18]  32.38 191.34 0 bottom
RN19  SRN10KJ-5-GP  [ARES2H18]  17.32 141.07 90 top
RN20  SRN10KJ-5-GP  [ARES2H18]  63.68 71.98 180 top
RN21  SRN10KJ-5-GP  [ARES2H18]  104.9 115.16 180 bottom
RN22  SRN10KJ-6-GP  [ARES8-CN24-MUH20]  80.77 181.23 0 top
RT1  NTC-10K-19-GP-U  [NTC-402H22-U]  61.64 183.18 180 top
RT2  NTC-10K-19-GP-U  [NTC-402H22-U]  119.23 145.58 180 top
SPI1  SKT-G6179-GP-U  [G6179-1000000-U]  12.27 75.23 0 top
SPK1  ACES-CON4-35-GP-U  [87212-04G2]  116 5.5 180 top
TOUCH1  ACES-CON5-28-GP  [50228-0057C-001]  15.5 61 90 top
TP1  -  [TPAD24]  66.19 145.2 270 bottom
TP2  -  [TPAD24]  55.08 153.09 180 bottom
TP3  -  [TPAD24]  56.93 155.31 180 bottom
TP4  -  [TPAD24]  56.25 156.46 180 bottom
TP5  -  [TPAD24]  61.7 152.03 180 bottom
TP6  -  [TPAD24]  63.17 151.54 180 bottom
TP7  -  [TPAD24]  60.35 155.35 180 bottom
TP8  -  [TPAD24]  61.06 156.44 180 bottom
TP9  -  [TPAD24]  65.64 134.63 270 bottom
TP10  -  [TPAD24]  66.85 134.58 270 bottom
TP11  -  [TPAD24]  64.54 152.73 180 bottom
TP12  -  [TPAD24]  50.75 139.23 180 bottom
TP13  -  [TPAD24]  49.58 139.67 180 bottom
TP14  -  [TPAD24]  63.76 149.77 180 bottom
TP15  -  [TPAD24]  62.03 150.45 180 bottom
TP16  -  [TPAD24]  62.11 137.83 180 bottom
TP17  -  [TPAD24]  65.99 133.45 270 bottom
TP18  -  [TPAD24]  63.29 138.2 270 bottom
TP19  TPAD28-1-GP-U  [TPAD28-1-U]  50.39 132.8 0 bottom
TP20  TPAD28-1-GP-U  [TPAD28-1-U]  52 133.92 180 bottom
TP21  TPAD28-1-GP-U  [TPAD28-1-U]  48.68 129.77 180 top
TP22  TPAD28-1-GP-U  [TPAD28-1-U]  62.13 130.91 0 bottom
TP23  -  [TPAD24]  60.53 134.5 180 bottom
TP24  -  [TPAD24]  58.27 137.22 180 bottom
TP25  TPAD28-1-GP-U  [TPAD28-1-U]  60.91 132.22 0 bottom
TP27  -  [TPAD24]  49.66 138.46 180 bottom
TP28  TPAD28-1-GP-U  [TPAD28-1-U]  50.59 129.72 180 top
TP29  -  [TPAD24]  49.58 147.5 270 bottom
TP30  -  [TPAD24]  60.94 138.31 180 bottom
TP31  TPAD28-1-GP-U  [TPAD28-1-U]  42.34 133.69 180 top
TP32  TPAD28-1-GP-U  [TPAD28-1-U]  118.01 38.02 0 top
TP33  -  [TPAD24]  53.52 78.59 90 bottom
TP34  -  [TPAD24]  53.62 80.39 90 bottom
TP35  -  [TPAD24]  53.77 81.71 90 bottom
TP55  TPAD28-1-GP-U  [TPAD28-1-U]  61.72 127.69 0 top
TP64  -  [TPAD24]  122.1 63.07 90 bottom
TP65  -  [TPAD24]  80.3 77.16 0 bottom
TP66  -  [TPAD24]  81.67 77.16 0 bottom
TP67  -  [TPAD24]  48.97 137.26 180 bottom
TP68  -  [TPAD24]  119.28 64.39 180 bottom
TP69  -  [TPAD24]  120.8 64.49 180 bottom
TP70  -  [TPAD24]  29.11 24.05 0 top
TR3  FILTER-4P-120-GP  [L125100-4P-1H28]  133.27 114.74 180 top
TR4  FILTER-4P-120-GP  [L125100-4P-1H28]  133.28 117.92 180 top
TR5  FILTER-4P-120-GP  [L125100-4P-1H28]  133.21 120.71 180 top
TR6  FILTER-4P-120-GP  [L125100-4P-1H28]  133.23 123.53 180 top
TR11  COIL-50OHM-GP  [L125100-4P-1H24]  127.28 171.2 0 bottom
TR12  COIL-50OHM-GP  [L125100-4P-1H24]  127.05 173.71 0 bottom
TR25  COIL-50OHM-GP  [L125100-4P-1H24]  13.97 144.3 270 bottom
TR26  COIL-50OHM-GP  [L125100-4P-1H24]  15.75 147.35 270 bottom
TR27  COIL-50OHM-GP  [L125100-4P-1H24]  17.02 41.53 0 top
TR28  COIL-50OHM-GP  [L125100-4P-1H24]  17.02 43.81 0 top
U9  AZC099-04S-1-GP  [SOT-6H58]  115.29 48.36 90 top
U10  AZC099-04S-1-GP  [SOT-6H58]  115.47 54.15 90 top
U12  APL3523AQBI-TRG-GP  [SON14J3020-G2610H32]  34.38 127.68 90 top
U13  APL3523AQBI-TRG-GP  [SON14J3020-G2610H32]  63.99 30.41 270 top
U16  AO3418L-GP  [SOT23DGS2D8H50]  27.23 47.17 270 top
U17  AO3418L-GP  [SOT23DGS2D8H50]  64.55 41.94 270 top
U18  AO6402A-GP  [SOT-6-1H50]  63.23 23.66 180 top
U20  AO6402A-GP  [SOT-6-1H50]  64.47 37.77 180 top
U22  AO6402A-GP  [SOT-6-1H50]  11.35 110.78 180 bottom
U23  AZ1045-04F-R7G-GP  [DFN10G2510H26]  137.32 117.89 270 top
U24  AZ1045-04F-R7G-GP  [DFN10G2510H26]  137.32 121.61 270 top
U25  AZ1045-04F-R7G-GP  [DFN10G2510H26]  136.35 110.36 270 top
U30  MX25L6406EM2I-12G-GP  [SOIC8-1H86]  12.27 75.23 180 top
U31  IT8732F-BX-GP  [PQFP128H134]  67.04 77.03 180 bottom
U38  RTD2136R-CGT-GP  [QFN48J6-G4D55H40]  21.08 96.27 90 bottom
U39  BAV99-T116-1-GP  [SOT-23-1H44]  133.68 9.57 90 top
U48  LM358DR2G-GP  [SOIC8H69]  120.65 7.11 270 bottom
U51  G524B1T11U-GP  [SOT-23-5H58]  85.29 61.06 270 bottom
U56  PM25LQ010B-SCE-GP  [SOIC8H69]  78.34 100.6 270 bottom
U58  M24C64-WMN6TP-1GP  [SOIC8H69]  17.46 109.28 0 bottom
U59  OZ554LN-GP  [QFN20-G2D1H34]  26.7 17.6 90 bottom
U6502  APL5606AKI-TRG-GP  [SOIC8H69]  105.56 45.12 0 bottom
U6503  IT8772E-EX-GP  [LQFP64H63]  70.09 77.46 180 bottom
USB2S1  SKT-USB6-182-GP  [SKT-USB6-145137-6]  141.31 95.5 90 top
USB2S2  SKT-USB6-182-GP  [SKT-USB6-145137-6]  141.31 70.5 90 top
USB3S1  SKT-USB11-57-GP-U  [SKT-USB11-139165-9]  139.65 172 90 top
X1  XTAL-32D768KHZ-64-GP  [SMD49-6914-0403H56]  38.68 131.23 270 bottom
X2  XTAL-48MHZ-26-GP  [OSC-3225-4P-3H36]  38.07 150.62 90 top
X3  XTAL-25MHZ-181-GP  [OSC-3225-4P-4H36]  120.24 60.1 90 bottom
XF1  XFORM-24P-27-GP  [XFORM24Z151100H160]  124.51 50.24 90 top

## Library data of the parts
AUDIO1 = QFN48J6-G465H40: tolerance: 071.00269.0003
AUDS1 = HTJ-035-24FBSPT: tolerance: 022.10002.00M1
BTT1 = AAA-BAT-034-K01: tolerance: 62.70010.061
C1 C2 C24 C52-C56 C90-C101 C148 C159 C173 C187 C191 C193 C196 C198 C201 C206 C207 C263-C265 C268 C269 C271-C275 C279 C280 C282-C287 C289 C303-C305 C311 C389 C398 C412 C427 C432 C441 C444 C447 C451 C455 C458 C468 C469 C471-C475 C478 C480 C482 C483 C485 C487 C493 C497 C499 C500 C502-C505 C508 C679 C681 C3605 C3606 C6512 C6521 C6532-C6536 EC9-EC12 PC6 PC4205 PC4429 PC4433 PC4809 PC4921 PC5011 = C402H22: tolerance: 78.10421.2FL
C3 C161 C174 C176 C237 C243 C245 C247 EC702 EC703 EC705-EC707 PC4401 PC4417 PC4424 PC4434 PC4807 PC4912 PC4913 PC5010 = C402H22: tolerance: 78.10224.2FL
C4-C7 C18-C21 C276 C277 C378 C380-C383 C385-C387 C433 C434 = C402H22: tolerance: 78.10421.2FL; signal model: C402H22_SCD1U16V2KX-3GP
C22 C23 C25 C27 PC4412 = C402H22: tolerance: 78.15124.2FL
C26 C28 C29 FC3 = C402H22: tolerance: 78.10322.2FL
C30 C31 C294 C295 = C402H22: tolerance: 78.15034.1FL
C32 = C402H22: tolerance: 78.10321.2FL
C33-C35 C183 C189 C208 C209 C256 C261 C262 C325 C355 C390 C391 C494 C6523 EC13-EC18 PC1 PC4436 = C402H22: tolerance: 78.10134.1FL
C36 C37 PC5108 = C402H22: tolerance: 78.22034.1FL
C38-C40 C58 C67-C70 C114-C116 C125 C132 C133 C137 C138 C152-C158 C257 C498 C501 C507 C6102 PC4418-PC4420 PC5101 PC5102 = C603H38: tolerance: 78.10610.5BL
C41-C51 C60-C66 C72-C80 C83-C87 C107 C109 C110 C112 C113 C124 C126-C131 C139-C141 C143-C146 C149-C151 C160 C278 C351 C372 C467 C476 C479 C481 C491 C3601 C3602 C6520 C6525 C6527 PC4421-PC4423 PC4806 PC5001 PC5204 = C402H22: tolerance: 78.10523.5FL
